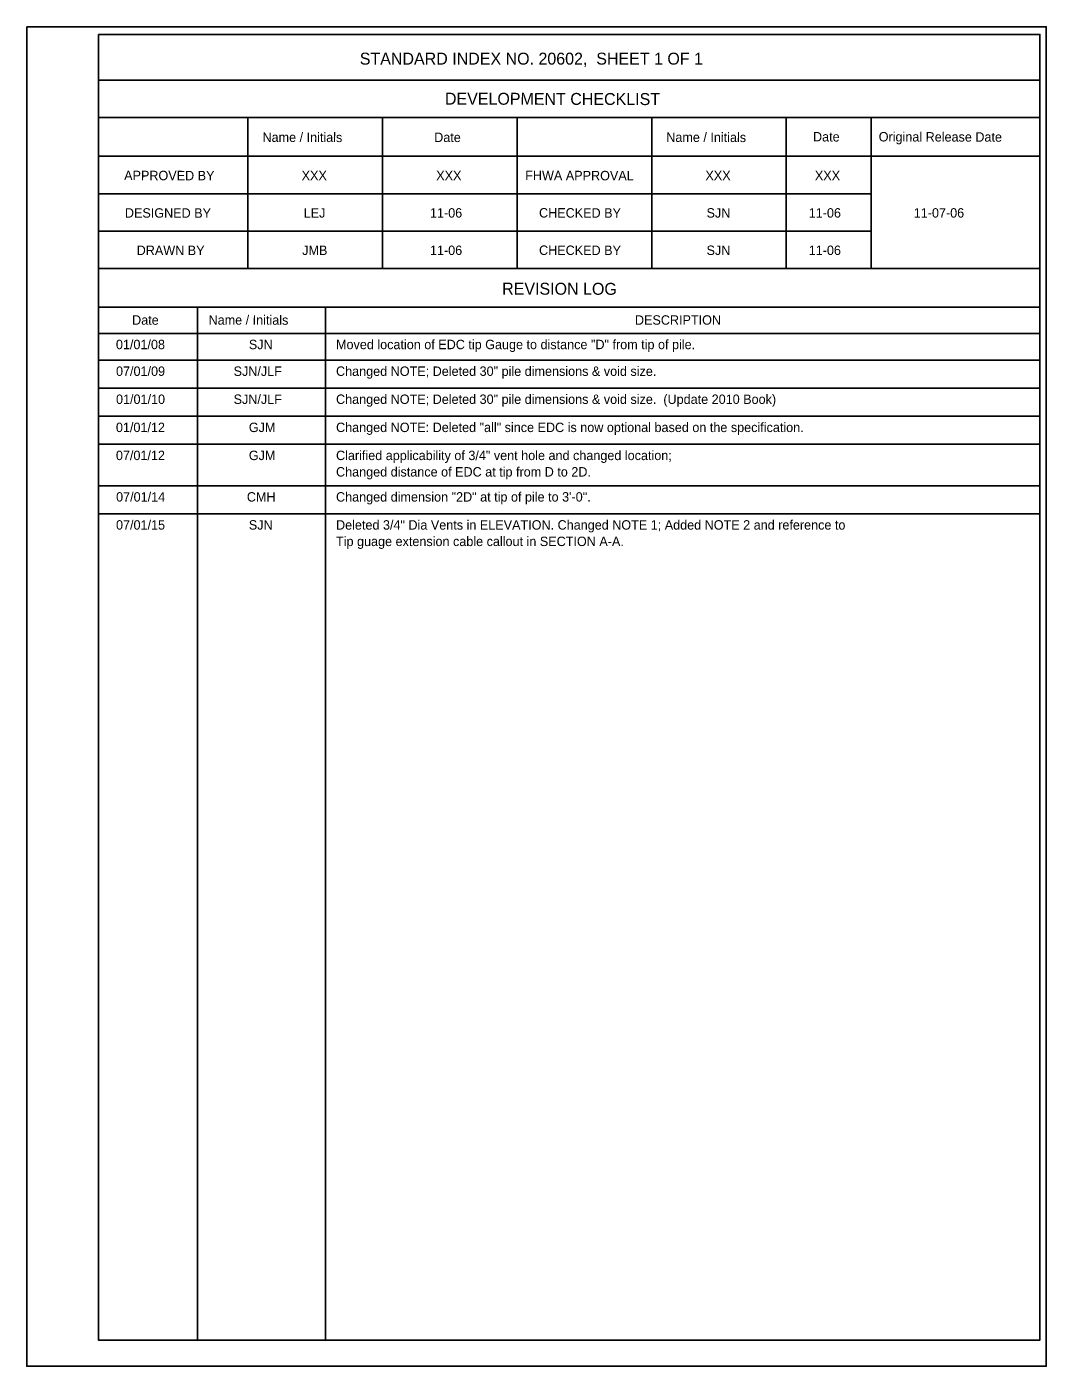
# Model space of a CAD drawing. Extents: x 0 to 36.1, y -3.7 to 15.
# Drawn here: x 25.16 to 36.06, y -0.33 to 14.01 of the extents above; entities that cross this region are included whole.
import ezdxf

# ---------------------------------------------------------------- set-up
doc = ezdxf.new("R2010")
doc.units = 0
for name, color, linetype in [('Border', 7, 'Continuous'), ('Dimension', 7, 'Continuous'), ('PlotBorder_dp', 7, 'Continuous'), ('TextStructures', 7, 'Continuous')]:
    doc.layers.add(name, color=color, linetype=linetype)

msp = doc.modelspace()

# ---------------------------------------------------------------- linework, layer by layer
at = {"layer": 'Border'}
for p, q in [((35.994, 13.435), (25.921, 13.435)), ((35.994, 13.035), (25.921, 13.035)), ((27.521, 13.035), (27.521, 11.421)), ((28.961, 13.035), (28.961, 11.421)), ((30.401, 13.035), (30.401, 11.421)), ((31.841, 13.035), (31.841, 11.421)), ((33.281, 13.035), (33.281, 11.421)), ((34.188, 13.035), (34.188, 11.421)), ((35.994, 12.621), (25.921, 12.621)), ((34.188, 12.221), (25.921, 12.221)), ((34.188, 11.821), (25.921, 11.821)), ((35.994, 11.421), (25.921, 11.421)), ((35.994, 11.007), (25.921, 11.007)), ((26.981, 11.007), (26.981, -0.046)), ((28.352, 11.007), (28.352, -0.046)), ((35.994, 10.726), (25.921, 10.726))]:
    msp.add_line(p, q, dxfattribs=at)
msp.add_lwpolyline([(25.921, 13.926), (35.994, 13.926), (35.994, -0.046), (25.921, -0.046)], close=True, dxfattribs=at)
at = {"layer": 'Dimension'}
for p, q in [((25.921, 10.44), (35.994, 10.44)), ((25.921, 10.14), (35.994, 10.14)), ((25.921, 9.839), (35.994, 9.839)), ((25.921, 9.539), (35.994, 9.539)), ((25.921, 9.095), (35.994, 9.095)), ((25.921, 8.795), (35.994, 8.795))]:
    msp.add_line(p, q, dxfattribs=at)
at = {"layer": 'PlotBorder_dp'}
msp.add_line((25.155, -0.326), (25.155, -0.326), dxfattribs=at)
msp.add_lwpolyline([(25.155, 14.007), (36.062, 14.007), (36.062, -0.326), (25.155, -0.326)], close=True, dxfattribs=at)

# ---------------------------------------------------------------- texts
at = {"layer": 'TextStructures'}
for s, height, p in [('STANDARD INDEX NO. 20602,  SHEET 1 OF 1', 0.128, (28.718, 13.602)), ('XXX', 0.1008, (28.096, 12.365)), ('XXX', 0.1008, (29.536, 12.365)), ('XXX', 0.1008, (32.416, 12.365)), ('XXX', 0.1008, (33.587, 12.365)), ('LEJ', 0.1008, (28.118, 11.965)), ('11-06', 0.1008, (29.469, 11.965)), ('SJN', 0.1008, (32.428, 11.965)), ('11-06', 0.1008, (33.521, 11.965)), ('11-07-06', 0.1008, (34.645, 11.965)), ('JMB', 0.1008, (28.102, 11.565)), ('11-06', 0.1008, (29.469, 11.565)), ('SJN', 0.1008, (32.428, 11.565)), ('11-06', 0.1008, (33.521, 11.565)), ('DESCRIPTION', 0.1008, (31.662, 10.819)), ('01/01/08', 0.1008, (26.109, 10.557)), ('SJN', 0.1008, (27.531, 10.557)), ('Moved location of EDC tip Gauge to distance "D" from tip of pile.', 0.1008, (28.464, 10.557)), ('07/01/09', 0.1008, (26.11, 10.271)), ('SJN/JLF', 0.1008, (27.368, 10.271)), ('Changed NOTE; Deleted 30" pile dimensions & void size.', 0.1008, (28.464, 10.271)), ('01/01/10', 0.1008, (26.11, 9.971)), ('SJN/JLF', 0.1008, (27.368, 9.971)), ('Changed NOTE; Deleted 30" pile dimensions & void size.  (Update 2010 Book)', 0.1008, (28.464, 9.971)), ('01/01/12', 0.1008, (26.109, 9.67)), ('GJM', 0.1008, (27.531, 9.67)), ('Changed NOTE: Deleted "all" since EDC is now optional based on the specification.', 0.1008, (28.464, 9.67)), ('07/01/12', 0.1008, (26.109, 9.37)), ('GJM', 0.1008, (27.531, 9.37)), ('Clarified applicability of 3/4" vent hole and changed location;', 0.1008, (28.464, 9.37)), ('Changed distance of EDC at tip from D to 2D.', 0.1008, (28.464, 9.194)), ('07/01/14', 0.1008, (26.111, 8.926)), ('Changed dimension "2D" at tip of pile to 3\'-0".', 0.1008, (28.464, 8.926)), ('CMH', 0.1008, (27.51, 8.926)), ('07/01/15', 0.1008, (26.11, 8.626)), ('SJN', 0.1008, (27.531, 8.626)), ('Deleted 3/4" Dia Vents in ELEVATION. Changed NOTE 1; Added NOTE 2 and reference to', 0.1008, (28.464, 8.626)), ('Tip guage extension cable callout in SECTION A-A.', 0.1008, (28.464, 8.45))]:
    msp.add_text(s, height=height, dxfattribs=at).set_placement(p)
for s, height, p in [('DEVELOPMENT CHECKLIST', 0.128, (29.629, 13.174)), ('Name / Initials', 0.1008, (27.677, 12.775)), ('Date', 0.1008, (29.514, 12.774)), ('Name / Initials', 0.1008, (31.997, 12.775)), ('Date', 0.1008, (33.567, 12.78)), ('Original Release Date', 0.1008, (34.27, 12.78)), ('APPROVED BY', 0.1008, (26.197, 12.366)), ('FHWA APPROVAL', 0.1008, (30.488, 12.366)), ('DESIGNED BY', 0.1008, (26.205, 11.965)), ('CHECKED BY', 0.1008, (30.636, 11.966)), ('DRAWN BY', 0.1008, (26.331, 11.565)), ('CHECKED BY', 0.1008, (30.636, 11.566)), ('REVISION LOG', 0.128, (30.241, 11.141)), ('Date', 0.1008, (26.282, 10.819)), ('Name / Initials', 0.1008, (27.1, 10.82))]:
    msp.add_text(s, height=height, rotation=359.8756, dxfattribs=at).set_placement(p)

doc.saveas('drawing.dxf')
